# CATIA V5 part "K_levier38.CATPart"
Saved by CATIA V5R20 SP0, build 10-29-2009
Part number: levier 38
Publications: "demi largeur balancier", "epaisseur pieces", "rayon congé", "Plan.+30", "liaison 23/57/38 sur 38", "liaison 28/38 sur 38", "liaison 38/51 sur 38"
Bounding box of the stored display mesh (mm): x -60 to 60, y -744.97 to 299.97, z -79.97 to 749.97
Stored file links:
  G:\Khaled_CFAO_2011\SIL\SIL_GR2\mdardier\Khaled\CAD_ThinkMOTION\K_levier38.CATPart
  G:\Khaled_CFAO_2011\SIL\SIL_GR2\mdardier\Khaled\CAD_ThinkMOTION\K_ass_tandem.CATProduct
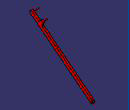
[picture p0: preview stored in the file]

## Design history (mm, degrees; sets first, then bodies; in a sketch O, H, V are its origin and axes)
External parameters (linked from other documents)
  `External.demi largeur balancier` = 50 mm
  `External.epaisseur pieces` = 30 mm
  `External.rayon congé` = 20 mm
Set1
  Plane1 "Plan.+30": linked copy from another document
  Point1 "liaison 23/57/38 sur 38": linked copy from another document
  Point2 "liaison 28/38 sur 38": linked copy from another document
  Point3 "liaison 38/51 sur 38": linked copy from another document
Body1 (main body)
  Sketch1 on Plane1, origin (30, 0, 0), H (0, 1, 0), V (0, 0, 1)
    construction line L1 (-720, 725) -> (275, -55)
    point P1 (-720, 725)
    point P2 (275, -55)
    line L2 (-704.5763, 744.6751) -> (-592.2529, 656.6226)
    line L3 (259.5763, -74.6751) -> (-735.4237, 705.3249)
    arc A1 centre (275, -55) radius 25 from (290.4237, -35.3249) to (259.5763, -74.6751) cw
    arc A2 centre (-720, 725) radius 25 from (-735.4237, 705.3249) to (-704.5763, 744.6751) cw
    reference projected point E1 (-720, 725) from Point1
    reference projected point E2 (275, -55) from Point2
    arc A3 centre (-550, 670) radius 25 from (-530.3249, 654.5763) to (-569.6751, 685.4237) ccw
    point P7 (-550, 670)
    reference projected point E3 (-550, 670) from Point3
    line L4 (-569.6751, 685.4237) -> (-592.2529, 656.6226)
    line L5 (-530.3249, 654.5763) -> (-552.9027, 625.7752)
    point P11 (-552.9027, 625.7752)
    line L6 (-552.9027, 625.7752) -> (290.4237, -35.3249)
    circle A4 centre (275, -55) radius 12.5
    point P12 (275, -55)
    reference projected point E4 (275, -55) from Point2
    distance L1 L2 = 25 {= `External.demi largeur balancier` /2}
    radius A3 = 25 {= `External.demi largeur balancier` /2}
    radius A4 = 12.5 {= `External.demi largeur balancier` /4}
    tangency: A1 L2, A2 L2, A1 L3, A2 L3, L4 A3, L5 A3
    coincidence: P1 E1, P2 E2, P7 E3, P11 L2, L2 L6, P12 E4
    perpendicularity: L2 L4, L5 L2
  Pad1: profile Sketch1, direction (1, 0, 0), length 30 {= `External.epaisseur pieces`}
  Sketch2 on start face of Pad1, origin (30, 0, 0), H (0, -1, 0), V (0, 0, 1)
    circle A1 centre (720, 725) radius 10
    point P1 (720, 725)
    reference projected point E1 (720, 725) from Point1
    radius A1 = 10 {= `External.demi largeur balancier` /5}
    coincidence: P1 E1
  Pad2: profile Sketch2, direction (-1, 0, 0), length 90 {= `External.epaisseur pieces` *3}
  Sketch3 on start face of Pad1, origin (30, 0, 0), H (0, -1, 0), V (0, 0, 1)
    circle A1 centre (550, 670) radius 10
    point P1 (550, 670)
    reference projected point E1 (550, 670) from Point3
    radius A1 = 10 {= `External.demi largeur balancier` /5}
    coincidence: P1 E1
  Pad3: profile Sketch3, direction (-1, 0, 0), length 60 {= `External.epaisseur pieces` *2}
  Fillet1: radius 20 {= `External.rayon congé`}, on edge [face of Pad1 from Sketch1.L5 | face of Pad1 from Sketch1.L6]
